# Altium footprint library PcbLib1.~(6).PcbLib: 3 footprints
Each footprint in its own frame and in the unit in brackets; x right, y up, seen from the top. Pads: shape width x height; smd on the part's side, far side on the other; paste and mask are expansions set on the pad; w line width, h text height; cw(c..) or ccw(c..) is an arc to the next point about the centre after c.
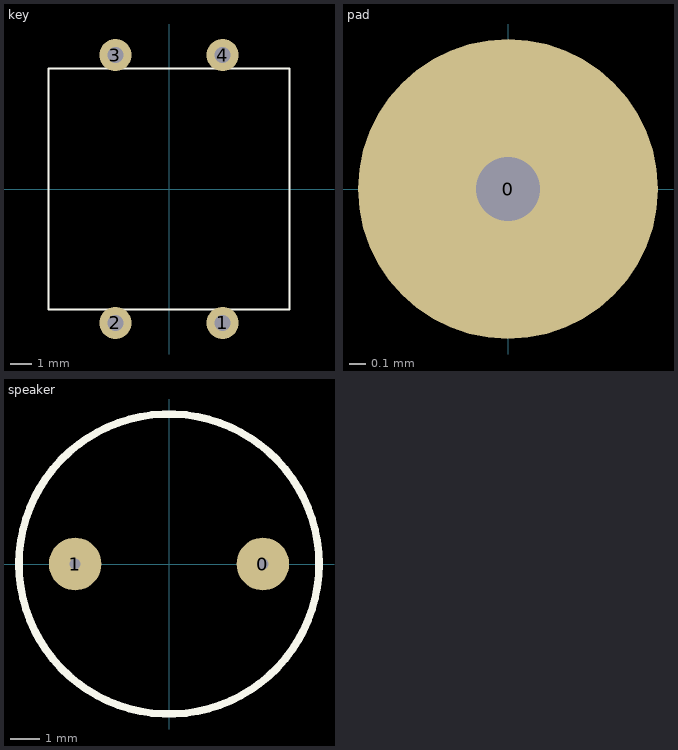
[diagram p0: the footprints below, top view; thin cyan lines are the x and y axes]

## key [mil]
pads (4):
  round 60 hole 30: 1(100,-250) 2(-100,-250) 3(-100,250) 4(100,250)
Top Overlay:
  lines w3.94: -225,-225 225,-225 225,225 -225,225 -225,-225
3D body "key.STEP": height 470, standoff 0, extent -249.99,-250 250.01,250

## pad [mil]
pads (1):
  round 70 hole 15: 0(0,0)

## speaker [mil]
pads (2):
  round 70 hole 15: 0(125,0) 1(-125,0)
Top Overlay:
  circle w10: c0,0 r199.62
